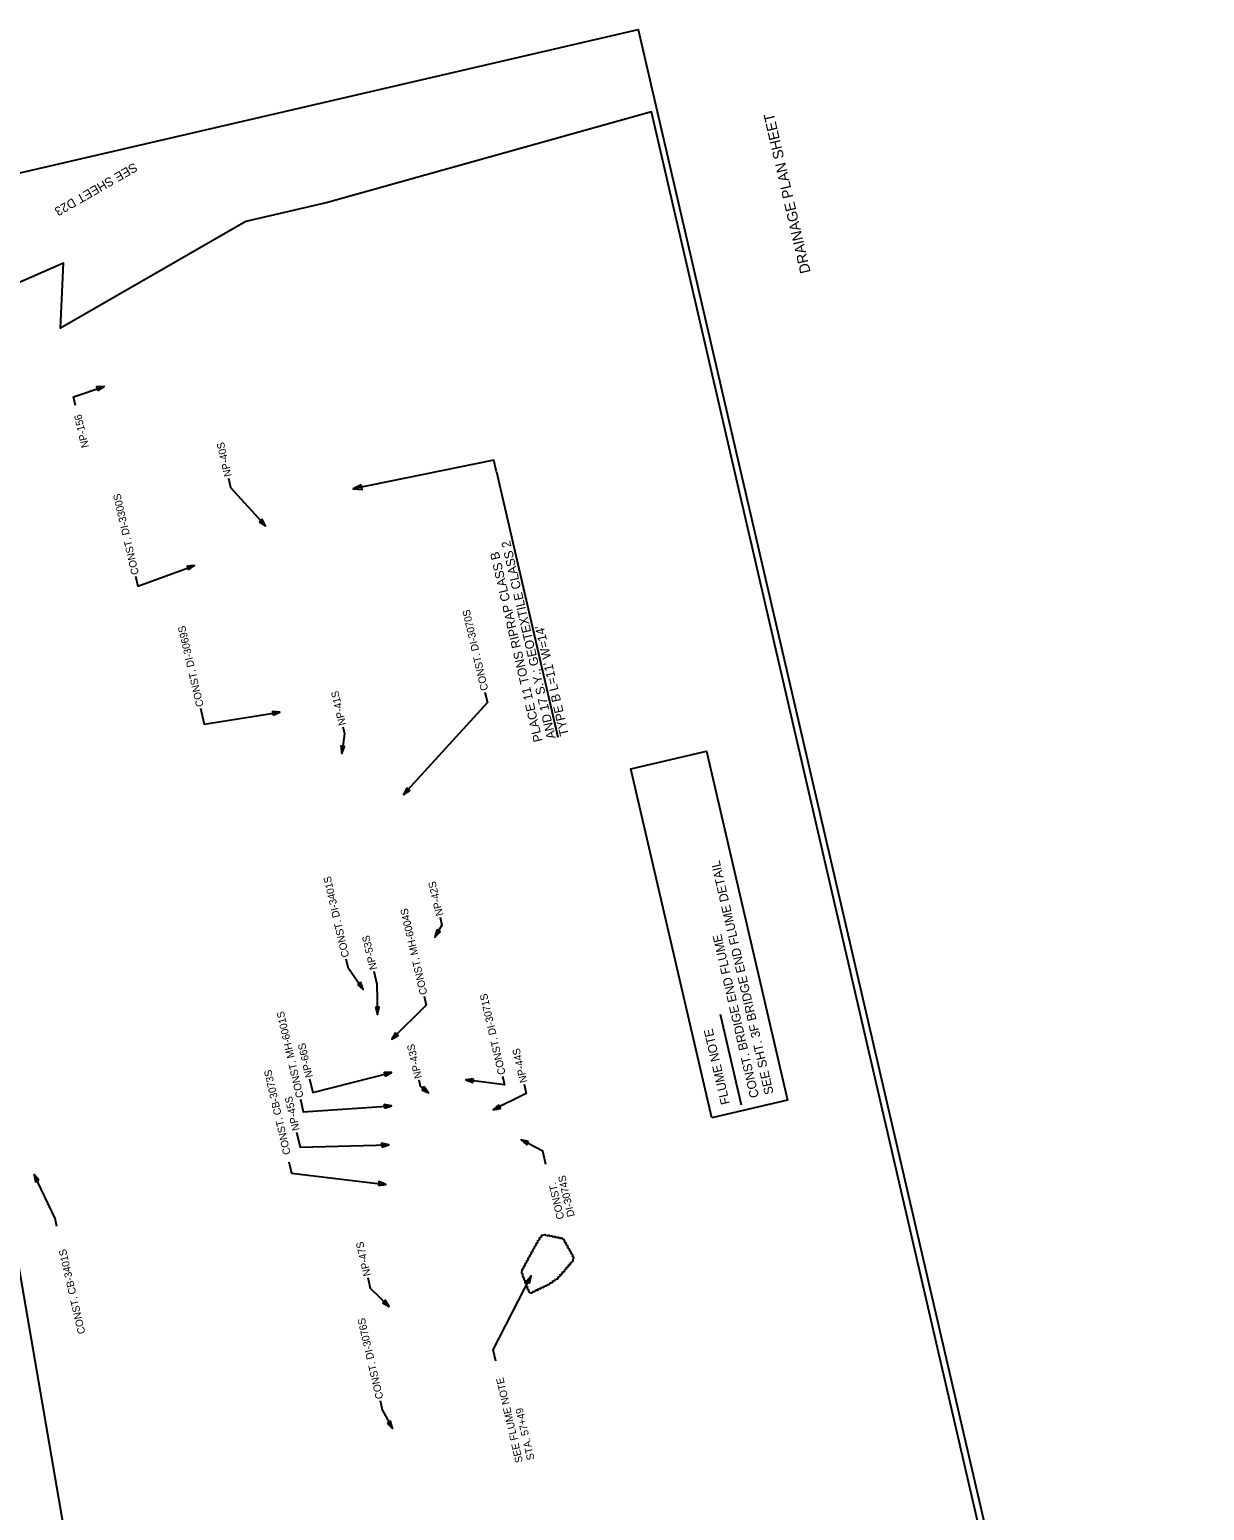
# Model space of a CAD drawing. Extents: x 1611522 to 1613146, y 1089913 to 1091760.
# Drawn here: x 1612133 to 1612918, y 1090772 to 1091760 of the extents above; entities that cross this region are included whole.
import ezdxf

# ---------------------------------------------------------------- set-up
doc = ezdxf.new("R2010")
doc.units = 0
for name, color, linetype in [('Level 2', 7, 'Continuous'), ('NOI', 7, 'Continuous'), ('Plan_Clip', 7, 'Continuous'), ('RD_SHT_MatchLine', 7, 'Continuous'), ('RD_TX_Drainage', 7, 'Continuous'), ('RD_TX_RoadID', 7, 'Continuous')]:
    doc.layers.add(name, color=color, linetype=linetype)

msp = doc.modelspace()

# ---------------------------------------------------------------- linework, layer by layer
at = {"layer": 'Level 2'}
msp.add_lwpolyline([(1611985.8, 1089912.73), (1611607.62, 1091544.48), (1612539.42, 1091760.44), (1612917.6, 1090128.69)], close=True, dxfattribs=at)
at = {"layer": 'NOI'}
msp.add_lwpolyline([(1612588.54, 1091033.75), (1612534.52, 1091266.84), (1612585.03, 1091278.55), (1612639.05, 1091045.46)], close=True, dxfattribs=at)
at = {"layer": 'Plan_Clip'}
msp.add_lwpolyline([(1612867.45, 1090326.93), (1612548.32, 1091705.46), (1612331.7, 1091644.99), (1612277.22, 1091632.37), (1612153.41, 1091561.04), (1612155.48, 1091604.44), (1612067.6, 1091566.09), (1612061.72, 1091571.33), (1611981.67, 1091541.05), (1611980.37, 1091551.71), (1611930.48, 1091534.68), (1611926.18, 1091544.55), (1611855.59, 1091525.38), (1611674.63, 1091416.97), (1611695.52, 1091328.83), (1611661.84, 1091320.85), (1611963.63, 1090019.87)], dxfattribs=at)
msp.add_lwpolyline([(1612867.45, 1090326.93), (1612548.32, 1091705.46), (1612331.7, 1091644.99), (1612277.22, 1091632.37), (1612153.41, 1091561.04), (1612155.48, 1091604.44), (1612067.6, 1091566.09), (1612061.72, 1091571.33), (1611981.67, 1091541.05), (1611980.37, 1091551.71), (1611930.48, 1091534.68), (1611926.18, 1091544.55), (1611855.59, 1091525.38), (1611674.63, 1091416.97), (1611695.52, 1091328.83), (1611661.84, 1091320.85), (1611963.63, 1090019.87)], dxfattribs=at)
msp.add_lwpolyline([(1612867.45, 1090326.93), (1612548.32, 1091705.46), (1612331.7, 1091644.99), (1612277.22, 1091632.37), (1612153.41, 1091561.04), (1612155.48, 1091604.44), (1612067.6, 1091566.09), (1612061.72, 1091571.33), (1611981.67, 1091541.05), (1611980.37, 1091551.71), (1611930.48, 1091534.68), (1611926.18, 1091544.55), (1611855.59, 1091525.38), (1611674.63, 1091416.97), (1611695.52, 1091328.83), (1611661.84, 1091320.85), (1611963.63, 1090019.87)], dxfattribs=at)
msp.add_lwpolyline([(1612867.45, 1090326.93), (1612548.32, 1091705.46), (1612331.7, 1091644.99), (1612277.22, 1091632.37), (1612153.41, 1091561.04), (1612155.48, 1091604.44), (1612067.6, 1091566.09), (1612061.72, 1091571.33), (1611981.67, 1091541.05), (1611980.37, 1091551.71), (1611930.48, 1091534.68), (1611926.18, 1091544.55), (1611855.59, 1091525.38), (1611674.63, 1091416.97), (1611695.52, 1091328.83), (1611661.84, 1091320.85), (1611963.63, 1090019.87)], dxfattribs=at)
msp.add_lwpolyline([(1612867.45, 1090326.93), (1612548.32, 1091705.46), (1612331.7, 1091644.99), (1612277.22, 1091632.37), (1612153.41, 1091561.04), (1612155.48, 1091604.44), (1612067.6, 1091566.09), (1612061.72, 1091571.33), (1611981.67, 1091541.05), (1611980.37, 1091551.71), (1611930.48, 1091534.68), (1611926.18, 1091544.55), (1611855.59, 1091525.38), (1611674.63, 1091416.97), (1611695.52, 1091328.83), (1611661.84, 1091320.85), (1611963.63, 1090019.87)], dxfattribs=at)
msp.add_lwpolyline([(1612867.45, 1090326.93), (1612548.32, 1091705.46), (1612331.7, 1091644.99), (1612277.22, 1091632.37), (1612153.41, 1091561.04), (1612155.48, 1091604.44), (1612067.6, 1091566.09), (1612061.72, 1091571.33), (1611981.67, 1091541.05), (1611980.37, 1091551.71), (1611930.48, 1091534.68), (1611926.18, 1091544.55), (1611855.59, 1091525.38), (1611674.63, 1091416.97), (1611695.52, 1091328.83), (1611661.84, 1091320.85), (1611963.63, 1090019.87)], dxfattribs=at)
msp.add_lwpolyline([(1612867.45, 1090326.93), (1612548.32, 1091705.46), (1612331.7, 1091644.99), (1612277.22, 1091632.37), (1612153.41, 1091561.04), (1612155.48, 1091604.44), (1612067.6, 1091566.09), (1612061.72, 1091571.33), (1611981.67, 1091541.05), (1611980.37, 1091551.71), (1611930.48, 1091534.68), (1611926.18, 1091544.55), (1611855.59, 1091525.38), (1611674.63, 1091416.97), (1611695.52, 1091328.83), (1611661.84, 1091320.85), (1611963.63, 1090019.87)], dxfattribs=at)
msp.add_lwpolyline([(1611963.63, 1090019.87), (1611998.55, 1090017.48), (1612099.34, 1090047.25), (1612244.44, 1090086.86), (1612241.08, 1090099.16), (1612268.58, 1090103.71), (1612018.61, 1091555.02), (1611981.67, 1091541.05), (1611980.37, 1091551.71), (1611930.48, 1091534.68), (1611926.18, 1091544.55), (1611855.59, 1091525.38), (1611674.63, 1091416.97), (1611695.52, 1091328.83), (1611661.84, 1091320.85)], close=True, dxfattribs=at)
at = {"layer": 'RD_TX_Drainage'}
for p, q in [((1612444.66, 1091465.2), (1612485.77, 1091287.82)), ((1612608.32, 1091042.1), (1612594.24, 1091102.83))]:
    msp.add_line(p, q, dxfattribs=at)
for points in [[(1612163.46, 1091509.41), (1612162.12, 1091515.18), (1612182.58, 1091522.15)], [(1612444.66, 1091465.2), (1612442.87, 1091472.92), (1612348.95, 1091453.69)], [(1612265.64, 1091460.98), (1612267.1, 1091454.64), (1612290.35, 1091429.01)], [(1612203.65, 1091395.41), (1612205.2, 1091388.72), (1612243.01, 1091402.63)], [(1612437, 1091318.08), (1612438.63, 1091311.08), (1612382.49, 1091249.55)], [(1612246.94, 1091307.28), (1612249.43, 1091296.52), (1612300.06, 1091304.55)], [(1612342.04, 1091294.86), (1612343.07, 1091290.44), (1612341.35, 1091277.08)], [(1612406.97, 1091167.68), (1612408.21, 1091162.32), (1612403.59, 1091154.4)], [(1612344.12, 1091140), (1612345.44, 1091134.33), (1612355.66, 1091119.45)], [(1612362.74, 1091131.6), (1612364.77, 1091122.87), (1612365.22, 1091102.73)], [(1612396.33, 1091114.95), (1612397.73, 1091108.89), (1612374.68, 1091086.17)], [(1612319.86, 1091059.65), (1612321.95, 1091050.65), (1612374.65, 1091063.97)], [(1612392.75, 1091059.06), (1612393.69, 1091054.97), (1612399.35, 1091050.44)], [(1612448.62, 1091061.57), (1612449.96, 1091055.77), (1612424.32, 1091059.17)], [(1612463.14, 1091056.21), (1612464.6, 1091049.9), (1612442.57, 1091039.08)], [(1612313.69, 1091046.17), (1612315.65, 1091037.74), (1612374.54, 1091041.76)], [(1612311.08, 1091024.22), (1612313.44, 1091014.06), (1612372.79, 1091015.59)], [(1612477.63, 1091002.57), (1612475.59, 1091011.37), (1612461.25, 1091019.1)], [(1612305.98, 1091004.27), (1612307.73, 1090996.72), (1612370.84, 1090989.25)], [(1612151.07, 1090961.12), (1612149.83, 1090966.45), (1612135.83, 1090995.92)], [(1612358.65, 1090927.08), (1612360.3, 1090919.94), (1612373, 1090907.75)], [(1612444.23, 1090871.21), (1612442.45, 1090878.88), (1612467.77, 1090928.2)], [(1612366.94, 1090844.98), (1612368.41, 1090838.63), (1612375.18, 1090826.24)]]:
    msp.add_lwpolyline(points, dxfattribs=at)
for points in [[(1612178.42, 1091519.36), (1612182.58, 1091522.15), (1612177.59, 1091521.81)], [(1612354.32, 1091456.38), (1612348.95, 1091453.69), (1612354.94, 1091453.33)], [(1612286.15, 1091431.72), (1612290.35, 1091429.01), (1612288.07, 1091433.45)], [(1612238.93, 1091399.75), (1612243.01, 1091402.63), (1612238.03, 1091402.17)], [(1612295.5, 1091302.52), (1612300.06, 1091304.55), (1612295.09, 1091305.07)], [(1612340.68, 1091282.04), (1612341.35, 1091277.08), (1612343.25, 1091281.71)], [(1612384.79, 1091253.99), (1612382.49, 1091249.55), (1612386.7, 1091252.25)], [(1612404.91, 1091159.23), (1612403.59, 1091154.4), (1612407.15, 1091157.92)], [(1612351.86, 1091122.69), (1612355.66, 1091119.45), (1612354, 1091124.16)], [(1612363.82, 1091107.53), (1612365.22, 1091102.73), (1612366.41, 1091107.59)], [(1612377.21, 1091090.48), (1612374.68, 1091086.17), (1612379.03, 1091088.64)], [(1612370.29, 1091061.53), (1612374.65, 1091063.97), (1612369.65, 1091064.04)], [(1612429.28, 1091059.82), (1612424.32, 1091059.17), (1612428.94, 1091057.25)], [(1612394.77, 1091052.45), (1612399.35, 1091050.44), (1612396.39, 1091054.47)], [(1612369.81, 1091040.14), (1612374.54, 1091041.76), (1612369.63, 1091042.72)], [(1612446.34, 1091042.38), (1612442.57, 1091039.08), (1612447.48, 1091040.05)], [(1612466.11, 1091017.95), (1612461.25, 1091019.1), (1612464.88, 1091015.67)], [(1612368, 1091014.18), (1612372.79, 1091015.59), (1612367.93, 1091016.76)], [(1612139.07, 1090992.12), (1612135.83, 1090995.92), (1612136.73, 1090991.01)], [(1612365.89, 1090988.53), (1612370.84, 1090989.25), (1612366.2, 1090991.1)], [(1612466.71, 1090923.31), (1612467.77, 1090928.2), (1612464.41, 1090924.5)], [(1612368.62, 1090910.16), (1612373, 1090907.75), (1612370.41, 1090912.03)], [(1612371.73, 1090829.86), (1612375.18, 1090826.24), (1612374, 1090831.1)]]:
    msp.add_lwpolyline(points, close=True, dxfattribs=at)
for centre, start, end in [((1612472.05, 1090949.04), 77.08792, 222.08792), ((1612473.14, 1090950.9), 77.08792, 222.08792), ((1612474.23, 1090952.76), 77.08792, 222.08792), ((1612475.57, 1090954.16), 50.41378, 195.41378), ((1612477.28, 1090954.48), 6.05702, 151.05702), ((1612479.39, 1090954.06), 6.05702, 151.05702), ((1612481.5, 1090953.63), 6.05702, 151.05702), ((1612483.61, 1090953.2), 6.05702, 151.05702), ((1612485.73, 1090952.77), 6.05702, 151.05702), ((1612487.83, 1090952.34), 5.36281, 150.36281), ((1612489.19, 1090951.34), 317.0137, 102.0137), ((1612490.25, 1090949.46), 317.0137, 102.0137), ((1612466.86, 1090939.61), 78.90627, 223.90627), ((1612467.89, 1090941.51), 78.90627, 223.90627), ((1612468.92, 1090943.4), 78.90627, 223.90627), ((1612469.95, 1090945.29), 78.90627, 223.90627), ((1612470.99, 1090947.18), 78.61862, 223.61862), ((1612491.31, 1090947.59), 317.0137, 102.0137), ((1612492.38, 1090945.71), 317.0137, 102.0137), ((1612493.44, 1090943.84), 317.0137, 102.0137), ((1612494.5, 1090941.96), 317.0137, 102.0137), ((1612495.17, 1090940.07), 297.06143, 82.06143), ((1612462.54, 1090930.32), 123.23467, 268.23467), ((1612462.73, 1090932.05), 78.90627, 223.90627), ((1612463.76, 1090933.94), 78.90627, 223.90627), ((1612464.79, 1090935.83), 78.90627, 223.90627), ((1612465.83, 1090937.72), 78.90627, 223.90627), ((1612487.76, 1090930.25), 247.18578, 32.18578), ((1612489.15, 1090931.89), 247.18578, 32.18578), ((1612490.55, 1090933.53), 247.18578, 32.18578), ((1612491.94, 1090935.18), 247.18578, 32.18578), ((1612493.33, 1090936.82), 247.18578, 32.18578), ((1612494.73, 1090938.46), 247.18578, 32.18578), ((1612463.21, 1090928.31), 128.59418, 273.59418), ((1612463.98, 1090926.3), 128.59418, 273.59418), ((1612464.76, 1090924.29), 128.59418, 273.59418), ((1612465.53, 1090922.27), 128.59418, 273.59418), ((1612466.31, 1090920.26), 128.59418, 273.59418), ((1612471.87, 1090919.75), 222.92575, 7.92575), ((1612473.82, 1090920.67), 222.92575, 7.92575), ((1612475.77, 1090921.6), 222.92575, 7.92575), ((1612477.71, 1090922.52), 222.92575, 7.92575), ((1612479.57, 1090923.54), 229.48005, 14.48005), ((1612481.36, 1090924.7), 231.66742, 16.66742), ((1612483.14, 1090925.92), 231.66742, 16.66742), ((1612484.87, 1090927.17), 235.43562, 20.43562), ((1612486.36, 1090928.61), 247.18578, 32.18578), ((1612467.08, 1090918.25), 128.59418, 273.59418), ((1612467.98, 1090917.9), 222.92575, 7.92575), ((1612469.93, 1090918.82), 222.92575, 7.92575)]:
    msp.add_arc(centre, 1.13, start, end, dxfattribs=at)

# ---------------------------------------------------------------- texts
at = {"layer": 'NOI'}
for s, p in [('SEE SHT. 3F BRIDGE END FLUME DETAIL', (1612629.85, 1091050.05)), ('CONST. BRDIGE END FLUME', (1612620.11, 1091047.79)), ('FLUME NOTE', (1612600.63, 1091043.28))]:
    msp.add_text(s, height=6, rotation=103.05027, dxfattribs=at).set_placement(p)
at = {"layer": 'RD_SHT_MatchLine'}
msp.add_text('SEE SHEET D23', height=6, rotation=209.92821, dxfattribs=at).set_placement((1612202.59, 1091671.78))
at = {"layer": 'RD_TX_Drainage'}
for s, height, p in [('NP-156', 5, (1612172.43, 1091481.77)), ('NP-40S', 5, (1612267.85, 1091462.51)), ('CONST. DI-3300S', 5, (1612205.86, 1091396.95)), ('AND 17 S.Y.; GEOTEXTILE CLASS 2', 6, (1612484.31, 1091287.48)), ('PLACE 11 TONS RIPRAP CLASS B', 6, (1612475.54, 1091285.45)), ('CONST. DI-3070S', 5, (1612439.21, 1091319.62)), ('CONST. DI-3069S', 5, (1612249.15, 1091308.81)), ("TYPE B L=11' W=14'", 6, (1612493.08, 1091289.51)), ('NP-41S', 5, (1612344.25, 1091296.4)), ('CONST. DI-3401S', 5, (1612346.33, 1091141.53)), ('NP-42S', 5, (1612409.18, 1091169.22)), ('CONST. MH-6004S', 5, (1612398.54, 1091116.48)), ('NP-53S', 5, (1612364.95, 1091133.14)), ('CONST. DI-3071S', 5, (1612450.83, 1091063.11)), ('CONST. MH-6001S', 5, (1612315.9, 1091047.71)), ('NP-66S', 5, (1612322.07, 1091061.19)), ('NP-43S', 5, (1612394.96, 1091060.6)), ('NP-44S', 5, (1612465.35, 1091057.75)), ('CONST. CB-3073S', 5, (1612307.28, 1091009.7)), ('NP-45S', 5, (1612313.29, 1091025.75)), ('CONST.', 5, (1612489.98, 1090966.56)), ('DI-3074S', 5, (1612497, 1090968.18)), ('NP-47S', 5, (1612360.86, 1090928.62)), ('CONST. CB-3401S', 5, (1612170.12, 1090889.99)), ('CONST. DI-3076S', 5, (1612369.15, 1090846.52)), ('SEE FLUME NOTE', 5, (1612462.38, 1090803.98)), ('STA. 57+49', 5, (1612470.17, 1090805.78))]:
    msp.add_text(s, height=height, rotation=103.04878, dxfattribs=at).set_placement(p)
at = {"layer": 'RD_TX_RoadID'}
msp.add_text('DRAINAGE PLAN SHEET', height=6.9833, rotation=103.04878, dxfattribs=at).set_placement((1612654.6, 1091598.49))

doc.saveas('drawing.dxf')
